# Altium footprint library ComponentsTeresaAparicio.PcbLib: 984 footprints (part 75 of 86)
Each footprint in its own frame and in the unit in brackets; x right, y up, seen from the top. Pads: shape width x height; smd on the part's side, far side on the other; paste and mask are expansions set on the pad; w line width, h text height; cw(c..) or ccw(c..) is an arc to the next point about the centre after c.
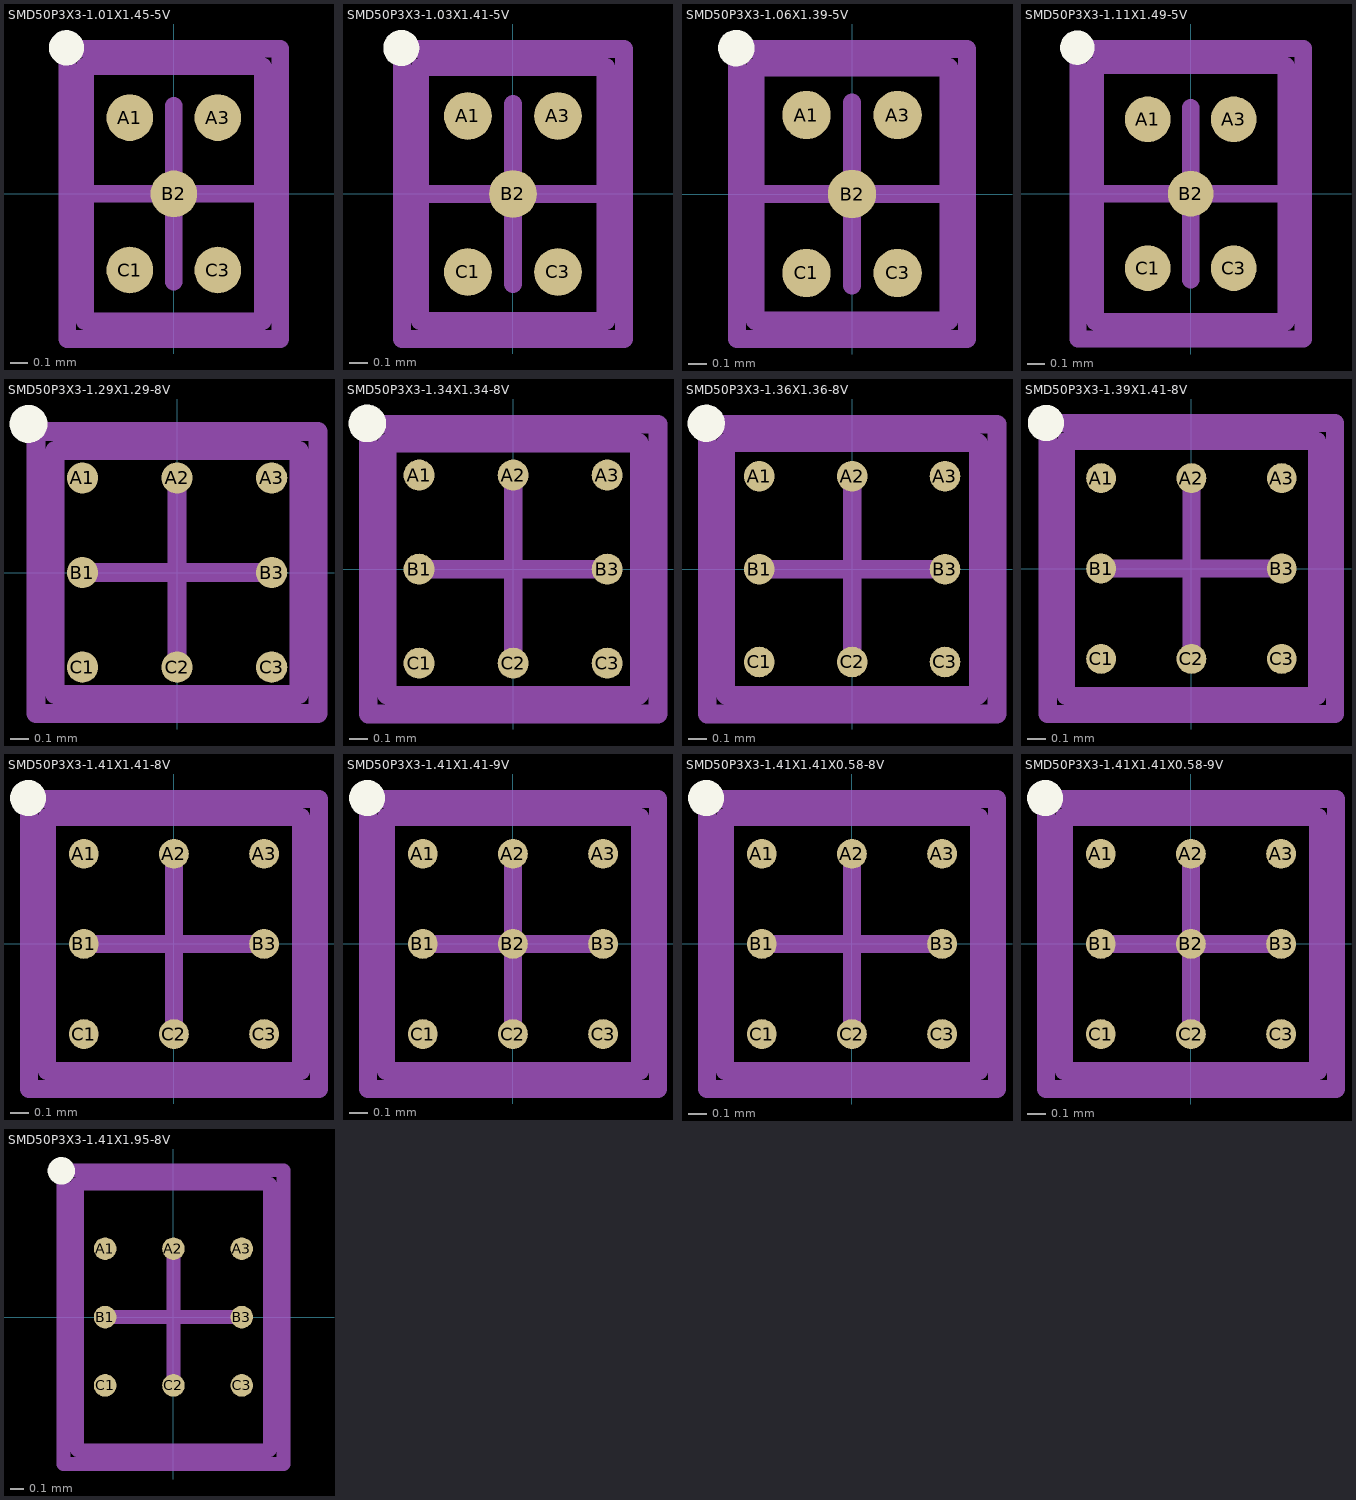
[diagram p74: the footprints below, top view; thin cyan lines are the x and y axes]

## SMD50P3X3-1.01X1.45-5V [mm] "Micro SMD, 5-Leads, Body 1.45x1.01mm, Pitch 0.5mm, NSC Recommended"
height 0.68
pads (5):
  round 0.265 smd paste-0.132 mask+0.05: A1(-0.25,0.433) A3(0.25,0.433) B2(0,0) C1(-0.25,-0.433) C3(0.25,-0.433)
Top Overlay:
  circle w0.1: c-0.61,0.83 r0.05
Top Paste:
  circle w0.05: c-0.2,0.383 r0.025
  circle w0.05: c-0.35,0.533 r0.025
  circle w0.05: c-0.2,0.533 r0.025
  circle w0.05: c-0.35,0.383 r0.025
  circle w0.05: c-0.2,-0.383 r0.025
  circle w0.05: c-0.35,-0.533 r0.025
  circle w0.05: c-0.35,-0.383 r0.025
  circle w0.05: c-0.2,-0.533 r0.025
  circle w0.05: c0.2,-0.383 r0.025
  circle w0.05: c0.35,-0.533 r0.025
  circle w0.05: c0.2,-0.533 r0.025
  circle w0.05: c0.35,-0.383 r0.025
  circle w0.05: c0.2,0.383 r0.025
  circle w0.05: c0.35,0.533 r0.025
  circle w0.05: c0.35,0.383 r0.025
  circle w0.05: c0.2,0.533 r0.025
  circle w0.05: c-0.075,0.075 r0.025
  circle w0.05: c0.075,-0.075 r0.025
  circle w0.05: c0.075,0.075 r0.025
  circle w0.05: c-0.075,-0.075 r0.025
  rectangle: -0.35,0.383 -0.2,0.533
  region: -0.2,0.383 -0.35,0.383 -0.35,0.333 -0.2,0.333
  region: -0.35,0.383 -0.35,0.533 -0.4,0.533 -0.4,0.383
  rectangle: -0.35,0.533 -0.2,0.583
  region: -0.2,0.533 -0.2,0.383 -0.15,0.383 -0.15,0.533
  region: -0.2,-0.533 -0.2,-0.383 -0.35,-0.383 -0.35,-0.533
  region: -0.2,-0.383 -0.2,-0.533 -0.15,-0.533 -0.15,-0.383
  region: -0.2,-0.533 -0.35,-0.533 -0.35,-0.583 -0.2,-0.583
  region: -0.35,-0.533 -0.35,-0.383 -0.4,-0.383 -0.4,-0.533
  rectangle: -0.35,-0.383 -0.2,-0.333
  region: 0.35,-0.383 0.2,-0.383 0.2,-0.533 0.35,-0.533
  rectangle: 0.2,-0.383 0.35,-0.333
  region: 0.35,-0.383 0.35,-0.533 0.4,-0.533 0.4,-0.383
  region: 0.35,-0.533 0.2,-0.533 0.2,-0.583 0.35,-0.583
  region: 0.2,-0.533 0.2,-0.383 0.15,-0.383 0.15,-0.533
  region: 0.2,0.533 0.2,0.383 0.35,0.383 0.35,0.533
  region: 0.2,0.383 0.2,0.533 0.15,0.533 0.15,0.383
  rectangle: 0.2,0.533 0.35,0.583
  region: 0.35,0.533 0.35,0.383 0.4,0.383 0.4,0.533
  region: 0.35,0.383 0.2,0.383 0.2,0.333 0.35,0.333
  region: 0.075,-0.075 -0.075,-0.075 -0.075,-0.125 0.075,-0.125
  region: 0.075,0.075 0.075,-0.075 0.125,-0.075 0.125,0.075
  rectangle: -0.075,0.075 0.075,0.125
  region: -0.075,-0.075 -0.075,0.075 -0.125,0.075 -0.125,-0.075
  region: -0.075,0.075 -0.075,-0.075 0.075,-0.075 0.075,0.075
Mechanical 13:
  lines w0.1: -0.505,-0.725 -0.505,0.725 0.505,0.725 0.505,-0.725 -0.505,-0.725
Mechanical 15:
  lines w0.1: -0.5,0 0.5,0 ; 0,-0.5 0,0.5 ; -0.605,-0.825 -0.605,0.825 0.605,0.825 0.605,-0.825 -0.605,-0.825
3D body: height 0.68, standoff 0, extent -0.504,-0.724 0.504,0.724

## SMD50P3X3-1.03X1.41-5V [mm] "Micro SMD, 5-Leads, Body 1.41x1.03mm, Pitch 0.5mm, NSC Recommended"
height 0.68
pads (5):
  round 0.265 smd paste-0.132 mask+0.05: A1(-0.25,0.433) A3(0.25,0.433) B2(0,0) C1(-0.25,-0.433) C3(0.25,-0.433)
Top Overlay:
  circle w0.1: c-0.62,0.81 r0.05
Top Paste:
  circle w0.05: c-0.2,0.383 r0.025
  circle w0.05: c-0.35,0.533 r0.025
  circle w0.05: c-0.2,0.533 r0.025
  circle w0.05: c-0.35,0.383 r0.025
  circle w0.05: c-0.2,-0.383 r0.025
  circle w0.05: c-0.35,-0.533 r0.025
  circle w0.05: c-0.35,-0.383 r0.025
  circle w0.05: c-0.2,-0.533 r0.025
  circle w0.05: c0.2,-0.383 r0.025
  circle w0.05: c0.35,-0.533 r0.025
  circle w0.05: c0.2,-0.533 r0.025
  circle w0.05: c0.35,-0.383 r0.025
  circle w0.05: c0.2,0.383 r0.025
  circle w0.05: c0.35,0.533 r0.025
  circle w0.05: c0.35,0.383 r0.025
  circle w0.05: c0.2,0.533 r0.025
  circle w0.05: c-0.075,0.075 r0.025
  circle w0.05: c0.075,-0.075 r0.025
  circle w0.05: c0.075,0.075 r0.025
  circle w0.05: c-0.075,-0.075 r0.025
  rectangle: -0.35,0.383 -0.2,0.533
  region: -0.2,0.383 -0.35,0.383 -0.35,0.333 -0.2,0.333
  region: -0.35,0.383 -0.35,0.533 -0.4,0.533 -0.4,0.383
  rectangle: -0.35,0.533 -0.2,0.583
  region: -0.2,0.533 -0.2,0.383 -0.15,0.383 -0.15,0.533
  region: -0.2,-0.533 -0.2,-0.383 -0.35,-0.383 -0.35,-0.533
  region: -0.2,-0.383 -0.2,-0.533 -0.15,-0.533 -0.15,-0.383
  region: -0.2,-0.533 -0.35,-0.533 -0.35,-0.583 -0.2,-0.583
  region: -0.35,-0.533 -0.35,-0.383 -0.4,-0.383 -0.4,-0.533
  rectangle: -0.35,-0.383 -0.2,-0.333
  region: 0.35,-0.383 0.2,-0.383 0.2,-0.533 0.35,-0.533
  rectangle: 0.2,-0.383 0.35,-0.333
  region: 0.35,-0.383 0.35,-0.533 0.4,-0.533 0.4,-0.383
  region: 0.35,-0.533 0.2,-0.533 0.2,-0.583 0.35,-0.583
  region: 0.2,-0.533 0.2,-0.383 0.15,-0.383 0.15,-0.533
  region: 0.2,0.533 0.2,0.383 0.35,0.383 0.35,0.533
  region: 0.2,0.383 0.2,0.533 0.15,0.533 0.15,0.383
  rectangle: 0.2,0.533 0.35,0.583
  region: 0.35,0.533 0.35,0.383 0.4,0.383 0.4,0.533
  region: 0.35,0.383 0.2,0.383 0.2,0.333 0.35,0.333
  region: 0.075,-0.075 -0.075,-0.075 -0.075,-0.125 0.075,-0.125
  region: 0.075,0.075 0.075,-0.075 0.125,-0.075 0.125,0.075
  rectangle: -0.075,0.075 0.075,0.125
  region: -0.075,-0.075 -0.075,0.075 -0.125,0.075 -0.125,-0.075
  region: -0.075,0.075 -0.075,-0.075 0.075,-0.075 0.075,0.075
Mechanical 13:
  lines w0.1: -0.515,-0.705 0.515,-0.705 0.515,0.705 -0.515,0.705 -0.515,-0.705
Mechanical 15:
  lines w0.1: -0.5,0 0.5,0 ; 0,-0.5 0,0.5 ; -0.615,-0.805 0.615,-0.805 0.615,0.805 -0.615,0.805 -0.615,-0.805
3D body: height 0.68, standoff 0, extent -0.514,-0.704 0.514,0.704

## SMD50P3X3-1.06X1.39-5V [mm] "Micro SMD, 5-Leads, Body 1.39x1.06mm, Pitch 0.5mm, NSC Recommended"
height 0.68
pads (5):
  round 0.265 smd paste-0.132 mask+0.05: A1(-0.25,0.433) A3(0.25,0.433) B2(0,0) C1(-0.25,-0.433) C3(0.25,-0.433)
Top Overlay:
  circle w0.1: c-0.635,0.8 r0.05
Top Paste:
  circle w0.05: c0.2,-0.383 r0.025
  circle w0.05: c0.35,-0.533 r0.025
  circle w0.05: c0.35,-0.383 r0.025
  circle w0.05: c0.2,-0.533 r0.025
  circle w0.05: c-0.35,-0.383 r0.025
  circle w0.05: c-0.2,-0.533 r0.025
  circle w0.05: c-0.2,-0.383 r0.025
  circle w0.05: c-0.35,-0.533 r0.025
  circle w0.05: c-0.075,0.075 r0.025
  circle w0.05: c0.075,-0.075 r0.025
  circle w0.05: c0.075,0.075 r0.025
  circle w0.05: c-0.075,-0.075 r0.025
  circle w0.05: c0.2,0.533 r0.025
  circle w0.05: c0.35,0.383 r0.025
  circle w0.05: c0.35,0.533 r0.025
  circle w0.05: c0.2,0.383 r0.025
  circle w0.05: c-0.35,0.533 r0.025
  circle w0.05: c-0.2,0.383 r0.025
  circle w0.05: c-0.2,0.533 r0.025
  circle w0.05: c-0.35,0.383 r0.025
  region: 0.35,-0.533 0.2,-0.533 0.2,-0.583 0.35,-0.583
  region: 0.35,-0.383 0.35,-0.533 0.4,-0.533 0.4,-0.383
  rectangle: 0.2,-0.383 0.35,-0.333
  region: 0.2,-0.533 0.2,-0.383 0.15,-0.383 0.15,-0.533
  region: 0.2,-0.383 0.2,-0.533 0.35,-0.533 0.35,-0.383
  region: -0.2,-0.533 -0.35,-0.533 -0.35,-0.583 -0.2,-0.583
  region: -0.2,-0.383 -0.2,-0.533 -0.15,-0.533 -0.15,-0.383
  rectangle: -0.35,-0.383 -0.2,-0.333
  region: -0.35,-0.533 -0.35,-0.383 -0.4,-0.383 -0.4,-0.533
  region: -0.35,-0.383 -0.35,-0.533 -0.2,-0.533 -0.2,-0.383
  region: 0.075,-0.075 -0.075,-0.075 -0.075,-0.125 0.075,-0.125
  region: 0.075,0.075 0.075,-0.075 0.125,-0.075 0.125,0.075
  rectangle: -0.075,0.075 0.075,0.125
  region: -0.075,-0.075 -0.075,0.075 -0.125,0.075 -0.125,-0.075
  region: -0.075,0.075 -0.075,-0.075 0.075,-0.075 0.075,0.075
  region: 0.35,0.383 0.2,0.383 0.2,0.333 0.35,0.333
  region: 0.35,0.533 0.35,0.383 0.4,0.383 0.4,0.533
  rectangle: 0.2,0.533 0.35,0.583
  region: 0.2,0.383 0.2,0.533 0.15,0.533 0.15,0.383
  region: 0.2,0.533 0.2,0.383 0.35,0.383 0.35,0.533
  region: -0.2,0.383 -0.35,0.383 -0.35,0.333 -0.2,0.333
  region: -0.2,0.533 -0.2,0.383 -0.15,0.383 -0.15,0.533
  rectangle: -0.35,0.533 -0.2,0.583
  region: -0.35,0.383 -0.35,0.533 -0.4,0.533 -0.4,0.383
  region: -0.35,0.533 -0.35,0.383 -0.2,0.383 -0.2,0.533
Mechanical 13:
  lines w0.1: -0.53,-0.695 0.53,-0.695 0.53,0.695 -0.53,0.695 -0.53,-0.695
Mechanical 15:
  lines w0.1: -0.5,0 0.5,0 ; 0,-0.5 0,0.5 ; -0.63,-0.795 0.63,-0.795 0.63,0.795 -0.63,0.795 -0.63,-0.795
3D body: height 0.68, standoff 0, extent -0.53,-0.695 0.53,0.695

## SMD50P3X3-1.11X1.49-5V [mm] "Micro SMD, 5-Leads, Body 1.49x1.11mm, Pitch 0.5mm, NSC Recommended"
height 0.68
pads (5):
  round 0.265 smd paste-0.132 mask+0.05: A1(-0.25,0.433) A3(0.25,0.433) B2(0,0) C1(-0.25,-0.433) C3(0.25,-0.433)
Top Overlay:
  circle w0.1: c-0.66,0.85 r0.05
Top Paste:
  circle w0.05: c-0.35,0.383 r0.025
  circle w0.05: c-0.2,0.533 r0.025
  circle w0.05: c-0.2,0.383 r0.025
  circle w0.05: c-0.35,0.533 r0.025
  circle w0.05: c0.2,0.383 r0.025
  circle w0.05: c0.35,0.533 r0.025
  circle w0.05: c0.35,0.383 r0.025
  circle w0.05: c0.2,0.533 r0.025
  circle w0.05: c-0.075,-0.075 r0.025
  circle w0.05: c0.075,0.075 r0.025
  circle w0.05: c0.075,-0.075 r0.025
  circle w0.05: c-0.075,0.075 r0.025
  circle w0.05: c-0.35,-0.533 r0.025
  circle w0.05: c-0.2,-0.383 r0.025
  circle w0.05: c-0.2,-0.533 r0.025
  circle w0.05: c-0.35,-0.383 r0.025
  circle w0.05: c0.2,-0.533 r0.025
  circle w0.05: c0.35,-0.383 r0.025
  circle w0.05: c0.35,-0.533 r0.025
  circle w0.05: c0.2,-0.383 r0.025
  region: -0.35,0.533 -0.35,0.383 -0.2,0.383 -0.2,0.533
  region: -0.35,0.383 -0.35,0.533 -0.4,0.533 -0.4,0.383
  rectangle: -0.35,0.533 -0.2,0.583
  region: -0.2,0.533 -0.2,0.383 -0.15,0.383 -0.15,0.533
  region: -0.2,0.383 -0.35,0.383 -0.35,0.333 -0.2,0.333
  region: 0.2,0.533 0.2,0.383 0.35,0.383 0.35,0.533
  region: 0.2,0.383 0.2,0.533 0.15,0.533 0.15,0.383
  rectangle: 0.2,0.533 0.35,0.583
  region: 0.35,0.533 0.35,0.383 0.4,0.383 0.4,0.533
  region: 0.35,0.383 0.2,0.383 0.2,0.333 0.35,0.333
  region: -0.075,0.075 -0.075,-0.075 0.075,-0.075 0.075,0.075
  region: -0.075,-0.075 -0.075,0.075 -0.125,0.075 -0.125,-0.075
  rectangle: -0.075,0.075 0.075,0.125
  region: 0.075,0.075 0.075,-0.075 0.125,-0.075 0.125,0.075
  region: 0.075,-0.075 -0.075,-0.075 -0.075,-0.125 0.075,-0.125
  region: -0.35,-0.383 -0.35,-0.533 -0.2,-0.533 -0.2,-0.383
  region: -0.35,-0.533 -0.35,-0.383 -0.4,-0.383 -0.4,-0.533
  rectangle: -0.35,-0.383 -0.2,-0.333
  region: -0.2,-0.383 -0.2,-0.533 -0.15,-0.533 -0.15,-0.383
  region: -0.2,-0.533 -0.35,-0.533 -0.35,-0.583 -0.2,-0.583
  region: 0.2,-0.383 0.2,-0.533 0.35,-0.533 0.35,-0.383
  region: 0.2,-0.533 0.2,-0.383 0.15,-0.383 0.15,-0.533
  rectangle: 0.2,-0.383 0.35,-0.333
  region: 0.35,-0.383 0.35,-0.533 0.4,-0.533 0.4,-0.383
  region: 0.35,-0.533 0.2,-0.533 0.2,-0.583 0.35,-0.583
Mechanical 13:
  lines w0.1: -0.555,-0.745 0.555,-0.745 0.555,0.745 -0.555,0.745 -0.555,-0.745
Mechanical 15:
  lines w0.1: -0.5,0 0.5,0 ; 0,-0.5 0,0.5 ; -0.655,-0.845 0.655,-0.845 0.655,0.845 -0.655,0.845 -0.655,-0.845
3D body: height 0.68, standoff 0, extent -0.555,-0.745 0.555,0.745

## SMD50P3X3-1.29X1.29-8V [mm] "Micro SMD, 8-Leads, Body 1.29x1.29mm, Pitch 0.5mm, NSC Recommended"
height 0.58
pads (8):
  round 0.165 smd paste-0.082 mask+0.05: A1(-0.5,0.5) A2(0,0.5) A3(0.5,0.5) B1(-0.5,0) B3(0.5,0) C1(-0.5,-0.5) C2(0,-0.5) C3(0.5,-0.5)
Top Overlay:
  circle w0.1: c-0.785,0.785 r0.05
Top Paste:
  circle w0.05: c0.625,0.425 r0.025
  circle w0.05: c0.425,0.625 r0.025
  circle w0.05: c0.425,0.425 r0.025
  circle w0.05: c0.625,0.625 r0.025
  circle w0.05: c-0.425,0.425 r0.025
  circle w0.05: c-0.625,0.625 r0.025
  circle w0.05: c-0.625,0.425 r0.025
  circle w0.05: c-0.425,0.625 r0.025
  circle w0.05: c0.1,0.425 r0.025
  circle w0.05: c-0.1,0.625 r0.025
  circle w0.05: c-0.1,0.425 r0.025
  circle w0.05: c0.1,0.625 r0.025
  circle w0.05: c0.1,-0.425 r0.025
  circle w0.05: c-0.1,-0.625 r0.025
  circle w0.05: c-0.1,-0.425 r0.025
  circle w0.05: c0.1,-0.625 r0.025
  circle w0.05: c-0.425,-0.425 r0.025
  circle w0.05: c-0.625,-0.625 r0.025
  circle w0.05: c-0.625,-0.425 r0.025
  circle w0.05: c-0.425,-0.625 r0.025
  circle w0.05: c0.625,-0.425 r0.025
  circle w0.05: c0.425,-0.625 r0.025
  circle w0.05: c0.425,-0.425 r0.025
  circle w0.05: c0.625,-0.625 r0.025
  circle w0.05: c0.625,-0.1 r0.025
  circle w0.05: c0.425,0.1 r0.025
  circle w0.05: c0.425,-0.1 r0.025
  circle w0.05: c0.625,0.1 r0.025
  circle w0.05: c-0.425,0.1 r0.025
  circle w0.05: c-0.625,-0.1 r0.025
  circle w0.05: c-0.625,0.1 r0.025
  circle w0.05: c-0.425,-0.1 r0.025
  rectangle: 0.425,0.375 0.625,0.425
  region: 0.625,0.675 0.425,0.675 0.425,0.625 0.625,0.625
  region: 0.375,0.625 0.375,0.425 0.425,0.425 0.425,0.625
  region: 0.425,0.625 0.425,0.425 0.625,0.425 0.625,0.625
  region: 0.675,0.425 0.675,0.625 0.625,0.625 0.625,0.425
  rectangle: -0.625,0.375 -0.425,0.425
  region: -0.425,0.675 -0.625,0.675 -0.625,0.625 -0.425,0.625
  region: -0.675,0.625 -0.675,0.425 -0.625,0.425 -0.625,0.625
  region: -0.625,0.625 -0.625,0.425 -0.425,0.425 -0.425,0.625
  region: -0.375,0.425 -0.375,0.625 -0.425,0.625 -0.425,0.425
  rectangle: -0.1,0.375 0.1,0.425
  region: 0.1,0.675 -0.1,0.675 -0.1,0.625 0.1,0.625
  region: -0.15,0.625 -0.15,0.425 -0.1,0.425 -0.1,0.625
  region: -0.1,0.625 -0.1,0.425 0.1,0.425 0.1,0.625
  region: 0.15,0.425 0.15,0.625 0.1,0.625 0.1,0.425
  region: 0.15,-0.625 0.15,-0.425 0.1,-0.425 0.1,-0.625
  region: -0.1,-0.425 -0.1,-0.625 0.1,-0.625 0.1,-0.425
  region: -0.15,-0.425 -0.15,-0.625 -0.1,-0.625 -0.1,-0.425
  region: 0.1,-0.375 -0.1,-0.375 -0.1,-0.425 0.1,-0.425
  rectangle: -0.1,-0.675 0.1,-0.625
  region: -0.375,-0.625 -0.375,-0.425 -0.425,-0.425 -0.425,-0.625
  region: -0.625,-0.425 -0.625,-0.625 -0.425,-0.625 -0.425,-0.425
  region: -0.675,-0.425 -0.675,-0.625 -0.625,-0.625 -0.625,-0.425
  region: -0.425,-0.375 -0.625,-0.375 -0.625,-0.425 -0.425,-0.425
  rectangle: -0.625,-0.675 -0.425,-0.625
  region: 0.675,-0.625 0.675,-0.425 0.625,-0.425 0.625,-0.625
  region: 0.425,-0.425 0.425,-0.625 0.625,-0.625 0.625,-0.425
  region: 0.375,-0.425 0.375,-0.625 0.425,-0.625 0.425,-0.425
  region: 0.625,-0.375 0.425,-0.375 0.425,-0.425 0.625,-0.425
  rectangle: 0.425,-0.675 0.625,-0.625
  rectangle: 0.425,-0.15 0.625,-0.1
  region: 0.625,0.15 0.425,0.15 0.425,0.1 0.625,0.1
  region: 0.375,0.1 0.375,-0.1 0.425,-0.1 0.425,0.1
  region: 0.425,0.1 0.425,-0.1 0.625,-0.1 0.625,0.1
  region: 0.675,-0.1 0.675,0.1 0.625,0.1 0.625,-0.1
  region: -0.375,-0.1 -0.375,0.1 -0.425,0.1 -0.425,-0.1
  region: -0.625,0.1 -0.625,-0.1 -0.425,-0.1 -0.425,0.1
  region: -0.675,0.1 -0.675,-0.1 -0.625,-0.1 -0.625,0.1
  region: -0.425,0.15 -0.625,0.15 -0.625,0.1 -0.425,0.1
  rectangle: -0.625,-0.15 -0.425,-0.1
Mechanical 13:
  lines w0.1: -0.645,-0.645 0.645,-0.645 0.645,0.645 -0.645,0.645 -0.645,-0.645
Mechanical 15:
  lines w0.1: -0.5,0 0.5,0 ; 0,-0.5 0,0.5 ; -0.745,-0.745 0.745,-0.745 0.745,0.745 -0.745,0.745 -0.745,-0.745
3D body: height 0.58, standoff 0, extent -0.644,-0.644 0.644,0.644

## SMD50P3X3-1.34X1.34-8V [mm] "Micro SMD, 8-Leads, Body 1.34x1.34mm, Pitch 0.5mm, NSC Recommended"
height 0.95
pads (8):
  round 0.165 smd paste-0.082 mask+0.05: A1(-0.5,0.5) A2(0,0.5) A3(0.5,0.5) B1(-0.5,0) B3(0.5,0) C1(-0.5,-0.5) C2(0,-0.5) C3(0.5,-0.5)
Top Overlay:
  circle w0.1: c-0.775,0.775 r0.05
Top Paste:
  circle w0.05: c-0.625,-0.625 r0.025
  circle w0.05: c-0.425,-0.425 r0.025
  circle w0.05: c-0.625,-0.425 r0.025
  circle w0.05: c-0.425,-0.625 r0.025
  circle w0.05: c0.425,-0.625 r0.025
  circle w0.05: c0.625,-0.425 r0.025
  circle w0.05: c0.425,-0.425 r0.025
  circle w0.05: c0.625,-0.625 r0.025
  circle w0.05: c0.425,0.425 r0.025
  circle w0.05: c0.625,0.625 r0.025
  circle w0.05: c0.425,0.625 r0.025
  circle w0.05: c0.625,0.425 r0.025
  circle w0.05: c-0.625,0.425 r0.025
  circle w0.05: c-0.425,0.625 r0.025
  circle w0.05: c-0.625,0.625 r0.025
  circle w0.05: c-0.425,0.425 r0.025
  circle w0.05: c0.1,0.425 r0.025
  circle w0.05: c-0.1,0.625 r0.025
  circle w0.05: c0.1,0.625 r0.025
  circle w0.05: c-0.1,0.425 r0.025
  circle w0.05: c-0.1,-0.425 r0.025
  circle w0.05: c0.1,-0.625 r0.025
  circle w0.05: c-0.1,-0.625 r0.025
  circle w0.05: c0.1,-0.425 r0.025
  circle w0.05: c0.425,-0.1 r0.025
  circle w0.05: c0.625,0.1 r0.025
  circle w0.05: c0.625,-0.1 r0.025
  circle w0.05: c0.425,0.1 r0.025
  circle w0.05: c-0.425,0.1 r0.025
  circle w0.05: c-0.625,-0.1 r0.025
  circle w0.05: c-0.625,0.1 r0.025
  circle w0.05: c-0.425,-0.1 r0.025
  region: -0.425,-0.625 -0.625,-0.625 -0.625,-0.675 -0.425,-0.675
  rectangle: -0.625,-0.625 -0.425,-0.425
  rectangle: -0.625,-0.425 -0.425,-0.375
  region: -0.625,-0.625 -0.625,-0.425 -0.675,-0.425 -0.675,-0.625
  region: -0.425,-0.425 -0.425,-0.625 -0.375,-0.625 -0.375,-0.425
  region: 0.625,-0.625 0.425,-0.625 0.425,-0.675 0.625,-0.675
  rectangle: 0.425,-0.625 0.625,-0.425
  rectangle: 0.425,-0.425 0.625,-0.375
  region: 0.425,-0.625 0.425,-0.425 0.375,-0.425 0.375,-0.625
  region: 0.625,-0.425 0.625,-0.625 0.675,-0.625 0.675,-0.425
  region: 0.625,0.425 0.425,0.425 0.425,0.375 0.625,0.375
  rectangle: 0.425,0.425 0.625,0.625
  rectangle: 0.425,0.625 0.625,0.675
  region: 0.425,0.425 0.425,0.625 0.375,0.625 0.375,0.425
  region: 0.625,0.625 0.625,0.425 0.675,0.425 0.675,0.625
  region: -0.425,0.425 -0.625,0.425 -0.625,0.375 -0.425,0.375
  rectangle: -0.625,0.425 -0.425,0.625
  rectangle: -0.625,0.625 -0.425,0.675
  region: -0.625,0.425 -0.625,0.625 -0.675,0.625 -0.675,0.425
  region: -0.425,0.625 -0.425,0.425 -0.375,0.425 -0.375,0.625
  region: 0.1,0.625 0.1,0.425 0.15,0.425 0.15,0.625
  region: -0.1,0.425 -0.1,0.625 -0.15,0.625 -0.15,0.425
  rectangle: -0.1,0.625 0.1,0.675
  rectangle: -0.1,0.425 0.1,0.625
  region: 0.1,0.425 -0.1,0.425 -0.1,0.375 0.1,0.375
  region: 0.1,-0.375 -0.1,-0.375 -0.1,-0.425 0.1,-0.425
  rectangle: -0.1,-0.625 0.1,-0.425
  rectangle: -0.1,-0.675 0.1,-0.625
  region: -0.15,-0.425 -0.15,-0.625 -0.1,-0.625 -0.1,-0.425
  region: 0.15,-0.625 0.15,-0.425 0.1,-0.425 0.1,-0.625
  region: 0.375,0.1 0.375,-0.1 0.425,-0.1 0.425,0.1
  region: 0.625,-0.1 0.625,0.1 0.425,0.1 0.425,-0.1
  region: 0.675,-0.1 0.675,0.1 0.625,0.1 0.625,-0.1
  rectangle: 0.425,-0.15 0.625,-0.1
  region: 0.625,0.15 0.425,0.15 0.425,0.1 0.625,0.1
  region: -0.375,-0.1 -0.375,0.1 -0.425,0.1 -0.425,-0.1
  region: -0.625,0.1 -0.625,-0.1 -0.425,-0.1 -0.425,0.1
  region: -0.675,0.1 -0.675,-0.1 -0.625,-0.1 -0.625,0.1
  region: -0.425,0.15 -0.625,0.15 -0.625,0.1 -0.425,0.1
  rectangle: -0.625,-0.15 -0.425,-0.1
Mechanical 13:
  lines w0.1: -0.67,-0.67 0.67,-0.67 0.67,0.67 -0.67,0.67 -0.67,-0.67
Mechanical 15:
  lines w0.1: -0.5,0 0.5,0 ; 0,-0.5 0,0.5 ; -0.77,-0.77 0.77,-0.77 0.77,0.77 -0.77,0.77 -0.77,-0.77
3D body: height 0.95, standoff 0, extent -0.669,-0.669 0.669,0.669

## SMD50P3X3-1.36X1.36-8V [mm] "Micro SMD, 8-Leads, Body 1.36x1.36mm, Pitch 0.5mm, NSC Recommended"
height 0.58
pads (8):
  round 0.165 smd paste-0.082 mask+0.05: A1(-0.5,0.5) A2(0,0.5) A3(0.5,0.5) B1(-0.5,0) B3(0.5,0) C1(-0.5,-0.5) C2(0,-0.5) C3(0.5,-0.5)
Top Overlay:
  circle w0.1: c-0.785,0.785 r0.05
Top Paste:
  circle w0.05: c-0.425,-0.1 r0.025
  circle w0.05: c-0.625,0.1 r0.025
  circle w0.05: c-0.625,-0.1 r0.025
  circle w0.05: c-0.425,0.1 r0.025
  circle w0.05: c0.625,0.1 r0.025
  circle w0.05: c0.425,-0.1 r0.025
  circle w0.05: c0.425,0.1 r0.025
  circle w0.05: c0.625,-0.1 r0.025
  circle w0.05: c0.625,-0.625 r0.025
  circle w0.05: c0.425,-0.425 r0.025
  circle w0.05: c0.425,-0.625 r0.025
  circle w0.05: c0.625,-0.425 r0.025
  circle w0.05: c-0.425,-0.625 r0.025
  circle w0.05: c-0.625,-0.425 r0.025
  circle w0.05: c-0.625,-0.625 r0.025
  circle w0.05: c-0.425,-0.425 r0.025
  circle w0.05: c0.1,-0.625 r0.025
  circle w0.05: c-0.1,-0.425 r0.025
  circle w0.05: c-0.1,-0.625 r0.025
  circle w0.05: c0.1,-0.425 r0.025
  circle w0.05: c0.1,0.625 r0.025
  circle w0.05: c-0.1,0.425 r0.025
  circle w0.05: c-0.1,0.625 r0.025
  circle w0.05: c0.1,0.425 r0.025
  circle w0.05: c-0.425,0.625 r0.025
  circle w0.05: c-0.625,0.425 r0.025
  circle w0.05: c-0.625,0.625 r0.025
  circle w0.05: c-0.425,0.425 r0.025
  circle w0.05: c0.625,0.625 r0.025
  circle w0.05: c0.425,0.425 r0.025
  circle w0.05: c0.425,0.625 r0.025
  circle w0.05: c0.625,0.425 r0.025
  rectangle: -0.625,-0.15 -0.425,-0.1
  region: -0.425,0.15 -0.625,0.15 -0.625,0.1 -0.425,0.1
  region: -0.675,0.1 -0.675,-0.1 -0.625,-0.1 -0.625,0.1
  region: -0.625,0.1 -0.625,-0.1 -0.425,-0.1 -0.425,0.1
  region: -0.375,-0.1 -0.375,0.1 -0.425,0.1 -0.425,-0.1
  region: 0.675,-0.1 0.675,0.1 0.625,0.1 0.625,-0.1
  region: 0.425,0.1 0.425,-0.1 0.625,-0.1 0.625,0.1
  region: 0.375,0.1 0.375,-0.1 0.425,-0.1 0.425,0.1
  region: 0.625,0.15 0.425,0.15 0.425,0.1 0.625,0.1
  rectangle: 0.425,-0.15 0.625,-0.1
  rectangle: 0.425,-0.675 0.625,-0.625
  region: 0.625,-0.375 0.425,-0.375 0.425,-0.425 0.625,-0.425
  region: 0.375,-0.425 0.375,-0.625 0.425,-0.625 0.425,-0.425
  region: 0.425,-0.425 0.425,-0.625 0.625,-0.625 0.625,-0.425
  region: 0.675,-0.625 0.675,-0.425 0.625,-0.425 0.625,-0.625
  rectangle: -0.625,-0.675 -0.425,-0.625
  region: -0.425,-0.375 -0.625,-0.375 -0.625,-0.425 -0.425,-0.425
  region: -0.675,-0.425 -0.675,-0.625 -0.625,-0.625 -0.625,-0.425
  region: -0.625,-0.425 -0.625,-0.625 -0.425,-0.625 -0.425,-0.425
  region: -0.375,-0.625 -0.375,-0.425 -0.425,-0.425 -0.425,-0.625
  rectangle: -0.1,-0.675 0.1,-0.625
  region: 0.1,-0.375 -0.1,-0.375 -0.1,-0.425 0.1,-0.425
  region: -0.15,-0.425 -0.15,-0.625 -0.1,-0.625 -0.1,-0.425
  region: -0.1,-0.425 -0.1,-0.625 0.1,-0.625 0.1,-0.425
  region: 0.15,-0.625 0.15,-0.425 0.1,-0.425 0.1,-0.625
  region: 0.15,0.425 0.15,0.625 0.1,0.625 0.1,0.425
  region: -0.1,0.625 -0.1,0.425 0.1,0.425 0.1,0.625
  region: -0.15,0.625 -0.15,0.425 -0.1,0.425 -0.1,0.625
  region: 0.1,0.675 -0.1,0.675 -0.1,0.625 0.1,0.625
  rectangle: -0.1,0.375 0.1,0.425
  region: -0.375,0.425 -0.375,0.625 -0.425,0.625 -0.425,0.425
  region: -0.625,0.625 -0.625,0.425 -0.425,0.425 -0.425,0.625
  region: -0.675,0.625 -0.675,0.425 -0.625,0.425 -0.625,0.625
  region: -0.425,0.675 -0.625,0.675 -0.625,0.625 -0.425,0.625
  rectangle: -0.625,0.375 -0.425,0.425
  region: 0.675,0.425 0.675,0.625 0.625,0.625 0.625,0.425
  region: 0.425,0.625 0.425,0.425 0.625,0.425 0.625,0.625
  region: 0.375,0.625 0.375,0.425 0.425,0.425 0.425,0.625
  region: 0.625,0.675 0.425,0.675 0.425,0.625 0.625,0.625
  rectangle: 0.425,0.375 0.625,0.425
Mechanical 13:
  lines w0.1: -0.68,-0.68 -0.68,0.68 0.68,0.68 0.68,-0.68 -0.68,-0.68
Mechanical 15:
  lines w0.1: -0.5,0 0.5,0 ; 0,-0.5 0,0.5 ; -0.78,-0.78 -0.78,0.78 0.78,0.78 0.78,-0.78 -0.78,-0.78
3D body: height 0.58, standoff 0, extent -0.679,-0.679 0.679,0.679

## SMD50P3X3-1.39X1.41-8V [mm] "Micro SMD, 8-Leads, Body 1.41x1.39mm, Pitch 0.5mm, NSC Recommended"
height 0.95
pads (8):
  round 0.165 smd paste-0.082 mask+0.05: A1(-0.5,0.5) A2(0,0.5) A3(0.5,0.5) B1(-0.5,0) B3(0.5,0) C1(-0.5,-0.5) C2(0,-0.5) C3(0.5,-0.5)
Top Overlay:
  circle w0.1: c-0.805,0.805 r0.05
Top Paste:
  circle w0.05: c0.625,-0.1 r0.025
  circle w0.05: c0.425,0.1 r0.025
  circle w0.05: c0.625,0.1 r0.025
  circle w0.05: c0.425,-0.1 r0.025
  circle w0.05: c-0.1,-0.625 r0.025
  circle w0.05: c0.1,-0.425 r0.025
  circle w0.05: c0.1,-0.625 r0.025
  circle w0.05: c-0.1,-0.425 r0.025
  circle w0.05: c-0.625,0.1 r0.025
  circle w0.05: c-0.425,-0.1 r0.025
  circle w0.05: c-0.625,-0.1 r0.025
  circle w0.05: c-0.425,0.1 r0.025
  circle w0.05: c0.1,0.625 r0.025
  circle w0.05: c-0.1,0.425 r0.025
  circle w0.05: c-0.1,0.625 r0.025
  circle w0.05: c0.1,0.425 r0.025
  circle w0.05: c0.625,0.425 r0.025
  circle w0.05: c0.425,0.625 r0.025
  circle w0.05: c0.625,0.625 r0.025
  circle w0.05: c0.425,0.425 r0.025
  circle w0.05: c0.425,-0.625 r0.025
  circle w0.05: c0.625,-0.425 r0.025
  circle w0.05: c0.625,-0.625 r0.025
  circle w0.05: c0.425,-0.425 r0.025
  circle w0.05: c-0.625,-0.425 r0.025
  circle w0.05: c-0.425,-0.625 r0.025
  circle w0.05: c-0.625,-0.625 r0.025
  circle w0.05: c-0.425,-0.425 r0.025
  circle w0.05: c-0.425,0.625 r0.025
  circle w0.05: c-0.625,0.425 r0.025
  circle w0.05: c-0.625,0.625 r0.025
  circle w0.05: c-0.425,0.425 r0.025
  rectangle: 0.425,-0.15 0.625,-0.1
  region: 0.625,0.1 0.425,0.1 0.425,-0.1 0.625,-0.1
  region: 0.625,0.15 0.425,0.15 0.425,0.1 0.625,0.1
  region: 0.675,-0.1 0.675,0.1 0.625,0.1 0.625,-0.1
  region: 0.375,0.1 0.375,-0.1 0.425,-0.1 0.425,0.1
  region: -0.15,-0.425 -0.15,-0.625 -0.1,-0.625 -0.1,-0.425
  region: 0.1,-0.625 0.1,-0.425 -0.1,-0.425 -0.1,-0.625
  region: 0.15,-0.625 0.15,-0.425 0.1,-0.425 0.1,-0.625
  rectangle: -0.1,-0.675 0.1,-0.625
  region: 0.1,-0.375 -0.1,-0.375 -0.1,-0.425 0.1,-0.425
  region: -0.425,0.15 -0.625,0.15 -0.625,0.1 -0.425,0.1
  rectangle: -0.625,-0.1 -0.425,0.1
  rectangle: -0.625,-0.15 -0.425,-0.1
  region: -0.675,0.1 -0.675,-0.1 -0.625,-0.1 -0.625,0.1
  region: -0.375,-0.1 -0.375,0.1 -0.425,0.1 -0.425,-0.1
  region: 0.15,0.425 0.15,0.625 0.1,0.625 0.1,0.425
  region: -0.1,0.625 -0.1,0.425 0.1,0.425 0.1,0.625
  region: -0.15,0.625 -0.15,0.425 -0.1,0.425 -0.1,0.625
  region: 0.1,0.675 -0.1,0.675 -0.1,0.625 0.1,0.625
  rectangle: -0.1,0.375 0.1,0.425
  rectangle: 0.425,0.375 0.625,0.425
  region: 0.625,0.625 0.425,0.625 0.425,0.425 0.625,0.425
  region: 0.625,0.675 0.425,0.675 0.425,0.625 0.625,0.625
  region: 0.675,0.425 0.675,0.625 0.625,0.625 0.625,0.425
  region: 0.375,0.625 0.375,0.425 0.425,0.425 0.425,0.625
  region: 0.375,-0.425 0.375,-0.625 0.425,-0.625 0.425,-0.425
  region: 0.625,-0.625 0.625,-0.425 0.425,-0.425 0.425,-0.625
  region: 0.675,-0.625 0.675,-0.425 0.625,-0.425 0.625,-0.625
  rectangle: 0.425,-0.675 0.625,-0.625
  region: 0.625,-0.375 0.425,-0.375 0.425,-0.425 0.625,-0.425
  region: -0.425,-0.375 -0.625,-0.375 -0.625,-0.425 -0.425,-0.425
  rectangle: -0.625,-0.625 -0.425,-0.425
  rectangle: -0.625,-0.675 -0.425,-0.625
  region: -0.675,-0.425 -0.675,-0.625 -0.625,-0.625 -0.625,-0.425
  region: -0.375,-0.625 -0.375,-0.425 -0.425,-0.425 -0.425,-0.625
  region: -0.375,0.425 -0.375,0.625 -0.425,0.625 -0.425,0.425
  region: -0.625,0.625 -0.625,0.425 -0.425,0.425 -0.425,0.625
  region: -0.675,0.625 -0.675,0.425 -0.625,0.425 -0.625,0.625
  region: -0.425,0.675 -0.625,0.675 -0.625,0.625 -0.425,0.625
  rectangle: -0.625,0.375 -0.425,0.425
Mechanical 13:
  lines w0.1: -0.695,-0.705 0.695,-0.705 0.695,0.705 -0.695,0.705 -0.695,-0.705
Mechanical 15:
  lines w0.1: -0.5,0 0.5,0 ; 0,-0.5 0,0.5 ; -0.795,-0.805 0.795,-0.805 0.795,0.805 -0.795,0.805 -0.795,-0.805
3D body: height 0.95, standoff 0, extent -0.694,-0.704 0.694,0.704

## SMD50P3X3-1.41X1.41-8V [mm] "Micro SMD, 8-Leads, Body 1.41x1.41mm, Pitch 0.5mm, NSC Recommended"
height 0.95
pads (8):
  round 0.165 smd paste-0.082 mask+0.05: A1(-0.5,0.5) A2(0,0.5) A3(0.5,0.5) B1(-0.5,0) B3(0.5,0) C1(-0.5,-0.5) C2(0,-0.5) C3(0.5,-0.5)
Top Overlay:
  circle w0.1: c-0.81,0.81 r0.05
Top Paste:
  circle w0.05: c-0.425,-0.1 r0.025
  circle w0.05: c-0.625,0.1 r0.025
  circle w0.05: c-0.625,-0.1 r0.025
  circle w0.05: c-0.425,0.1 r0.025
  circle w0.05: c0.625,0.1 r0.025
  circle w0.05: c0.425,-0.1 r0.025
  circle w0.05: c0.425,0.1 r0.025
  circle w0.05: c0.625,-0.1 r0.025
  circle w0.05: c0.625,-0.625 r0.025
  circle w0.05: c0.425,-0.425 r0.025
  circle w0.05: c0.425,-0.625 r0.025
  circle w0.05: c0.625,-0.425 r0.025
  circle w0.05: c-0.425,-0.625 r0.025
  circle w0.05: c-0.625,-0.425 r0.025
  circle w0.05: c-0.625,-0.625 r0.025
  circle w0.05: c-0.425,-0.425 r0.025
  circle w0.05: c0.1,-0.625 r0.025
  circle w0.05: c-0.1,-0.425 r0.025
  circle w0.05: c-0.1,-0.625 r0.025
  circle w0.05: c0.1,-0.425 r0.025
  circle w0.05: c0.1,0.625 r0.025
  circle w0.05: c-0.1,0.425 r0.025
  circle w0.05: c-0.1,0.625 r0.025
  circle w0.05: c0.1,0.425 r0.025
  circle w0.05: c-0.425,0.625 r0.025
  circle w0.05: c-0.625,0.425 r0.025
  circle w0.05: c-0.625,0.625 r0.025
  circle w0.05: c-0.425,0.425 r0.025
  circle w0.05: c0.625,0.625 r0.025
  circle w0.05: c0.425,0.425 r0.025
  circle w0.05: c0.425,0.625 r0.025
  circle w0.05: c0.625,0.425 r0.025
  rectangle: -0.625,-0.15 -0.425,-0.1
  region: -0.425,0.15 -0.625,0.15 -0.625,0.1 -0.425,0.1
  region: -0.675,0.1 -0.675,-0.1 -0.625,-0.1 -0.625,0.1
  region: -0.625,0.1 -0.625,-0.1 -0.425,-0.1 -0.425,0.1
  region: -0.375,-0.1 -0.375,0.1 -0.425,0.1 -0.425,-0.1
  region: 0.675,-0.1 0.675,0.1 0.625,0.1 0.625,-0.1
  region: 0.425,0.1 0.425,-0.1 0.625,-0.1 0.625,0.1
  region: 0.375,0.1 0.375,-0.1 0.425,-0.1 0.425,0.1
  region: 0.625,0.15 0.425,0.15 0.425,0.1 0.625,0.1
  rectangle: 0.425,-0.15 0.625,-0.1
  rectangle: 0.425,-0.675 0.625,-0.625
  region: 0.625,-0.375 0.425,-0.375 0.425,-0.425 0.625,-0.425
  region: 0.375,-0.425 0.375,-0.625 0.425,-0.625 0.425,-0.425
  region: 0.425,-0.425 0.425,-0.625 0.625,-0.625 0.625,-0.425
  region: 0.675,-0.625 0.675,-0.425 0.625,-0.425 0.625,-0.625
  rectangle: -0.625,-0.675 -0.425,-0.625
  region: -0.425,-0.375 -0.625,-0.375 -0.625,-0.425 -0.425,-0.425
  region: -0.675,-0.425 -0.675,-0.625 -0.625,-0.625 -0.625,-0.425
  region: -0.625,-0.425 -0.625,-0.625 -0.425,-0.625 -0.425,-0.425
  region: -0.375,-0.625 -0.375,-0.425 -0.425,-0.425 -0.425,-0.625
  rectangle: -0.1,-0.675 0.1,-0.625
  region: 0.1,-0.375 -0.1,-0.375 -0.1,-0.425 0.1,-0.425
  region: -0.15,-0.425 -0.15,-0.625 -0.1,-0.625 -0.1,-0.425
  region: -0.1,-0.425 -0.1,-0.625 0.1,-0.625 0.1,-0.425
  region: 0.15,-0.625 0.15,-0.425 0.1,-0.425 0.1,-0.625
  region: 0.15,0.425 0.15,0.625 0.1,0.625 0.1,0.425
  region: -0.1,0.625 -0.1,0.425 0.1,0.425 0.1,0.625
  region: -0.15,0.625 -0.15,0.425 -0.1,0.425 -0.1,0.625
  region: 0.1,0.675 -0.1,0.675 -0.1,0.625 0.1,0.625
  rectangle: -0.1,0.375 0.1,0.425
  region: -0.375,0.425 -0.375,0.625 -0.425,0.625 -0.425,0.425
  region: -0.625,0.625 -0.625,0.425 -0.425,0.425 -0.425,0.625
  region: -0.675,0.625 -0.675,0.425 -0.625,0.425 -0.625,0.625
  region: -0.425,0.675 -0.625,0.675 -0.625,0.625 -0.425,0.625
  rectangle: -0.625,0.375 -0.425,0.425
  region: 0.675,0.425 0.675,0.625 0.625,0.625 0.625,0.425
  region: 0.425,0.625 0.425,0.425 0.625,0.425 0.625,0.625
  region: 0.375,0.625 0.375,0.425 0.425,0.425 0.425,0.625
  region: 0.625,0.675 0.425,0.675 0.425,0.625 0.625,0.625
  rectangle: 0.425,0.375 0.625,0.425
Mechanical 13:
  lines w0.1: -0.705,-0.705 -0.705,0.705 0.705,0.705 0.705,-0.705 -0.705,-0.705
Mechanical 15:
  lines w0.1: -0.5,0 0.5,0 ; 0,-0.5 0,0.5 ; -0.805,-0.805 -0.805,0.805 0.805,0.805 0.805,-0.805 -0.805,-0.805
3D body: height 0.95, standoff 0, extent -0.704,-0.704 0.704,0.704

## SMD50P3X3-1.41X1.41-9V [mm] "Micro SMD, 9-Leads, Body 1.41x1.41mm, Pitch 0.5mm, NSC Recommended"
height 0.95
pads (9):
  round 0.165 smd paste-0.082 mask+0.05: A1(-0.5,0.5) A2(0,0.5) A3(0.5,0.5) B1(-0.5,0) B2(0,0) B3(0.5,0) C1(-0.5,-0.5) C2(0,-0.5) C3(0.5,-0.5)
Top Overlay:
  circle w0.1: c-0.81,0.81 r0.05
Top Paste:
  circle w0.05: c-0.425,-0.1 r0.025
  circle w0.05: c-0.625,0.1 r0.025
  circle w0.05: c-0.625,-0.1 r0.025
  circle w0.05: c-0.425,0.1 r0.025
  circle w0.05: c0.625,0.1 r0.025
  circle w0.05: c0.425,-0.1 r0.025
  circle w0.05: c0.425,0.1 r0.025
  circle w0.05: c0.625,-0.1 r0.025
  circle w0.05: c0.625,-0.625 r0.025
  circle w0.05: c0.425,-0.425 r0.025
  circle w0.05: c0.425,-0.625 r0.025
  circle w0.05: c0.625,-0.425 r0.025
  circle w0.05: c-0.425,-0.625 r0.025
  circle w0.05: c-0.625,-0.425 r0.025
  circle w0.05: c-0.625,-0.625 r0.025
  circle w0.05: c-0.425,-0.425 r0.025
  circle w0.05: c0.1,-0.625 r0.025
  circle w0.05: c-0.1,-0.425 r0.025
  circle w0.05: c-0.1,-0.625 r0.025
  circle w0.05: c0.1,-0.425 r0.025
  circle w0.05: c0.1,0.625 r0.025
  circle w0.05: c-0.1,0.425 r0.025
  circle w0.05: c-0.1,0.625 r0.025
  circle w0.05: c0.1,0.425 r0.025
  circle w0.05: c-0.425,0.625 r0.025
  circle w0.05: c-0.625,0.425 r0.025
  circle w0.05: c-0.625,0.625 r0.025
  circle w0.05: c-0.425,0.425 r0.025
  circle w0.05: c0.625,0.625 r0.025
  circle w0.05: c0.425,0.425 r0.025
  circle w0.05: c0.425,0.625 r0.025
  circle w0.05: c0.625,0.425 r0.025
  circle w0.05: c0.1,0.1 r0.025
  circle w0.05: c-0.1,-0.1 r0.025
  circle w0.05: c-0.1,0.1 r0.025
  circle w0.05: c0.1,-0.1 r0.025
  rectangle: -0.625,-0.15 -0.425,-0.1
  region: -0.425,0.15 -0.625,0.15 -0.625,0.1 -0.425,0.1
  region: -0.675,0.1 -0.675,-0.1 -0.625,-0.1 -0.625,0.1
  region: -0.625,0.1 -0.625,-0.1 -0.425,-0.1 -0.425,0.1
  region: -0.375,-0.1 -0.375,0.1 -0.425,0.1 -0.425,-0.1
  region: 0.675,-0.1 0.675,0.1 0.625,0.1 0.625,-0.1
  region: 0.425,0.1 0.425,-0.1 0.625,-0.1 0.625,0.1
  region: 0.375,0.1 0.375,-0.1 0.425,-0.1 0.425,0.1
  region: 0.625,0.15 0.425,0.15 0.425,0.1 0.625,0.1
  rectangle: 0.425,-0.15 0.625,-0.1
  rectangle: 0.425,-0.675 0.625,-0.625
  region: 0.625,-0.375 0.425,-0.375 0.425,-0.425 0.625,-0.425
  region: 0.375,-0.425 0.375,-0.625 0.425,-0.625 0.425,-0.425
  region: 0.425,-0.425 0.425,-0.625 0.625,-0.625 0.625,-0.425
  region: 0.675,-0.625 0.675,-0.425 0.625,-0.425 0.625,-0.625
  rectangle: -0.625,-0.675 -0.425,-0.625
  region: -0.425,-0.375 -0.625,-0.375 -0.625,-0.425 -0.425,-0.425
  region: -0.675,-0.425 -0.675,-0.625 -0.625,-0.625 -0.625,-0.425
  region: -0.625,-0.425 -0.625,-0.625 -0.425,-0.625 -0.425,-0.425
  region: -0.375,-0.625 -0.375,-0.425 -0.425,-0.425 -0.425,-0.625
  rectangle: -0.1,-0.675 0.1,-0.625
  region: 0.1,-0.375 -0.1,-0.375 -0.1,-0.425 0.1,-0.425
  region: -0.15,-0.425 -0.15,-0.625 -0.1,-0.625 -0.1,-0.425
  region: -0.1,-0.425 -0.1,-0.625 0.1,-0.625 0.1,-0.425
  region: 0.15,-0.625 0.15,-0.425 0.1,-0.425 0.1,-0.625
  region: 0.15,0.425 0.15,0.625 0.1,0.625 0.1,0.425
  region: -0.1,0.625 -0.1,0.425 0.1,0.425 0.1,0.625
  region: -0.15,0.625 -0.15,0.425 -0.1,0.425 -0.1,0.625
  region: 0.1,0.675 -0.1,0.675 -0.1,0.625 0.1,0.625
  rectangle: -0.1,0.375 0.1,0.425
  region: -0.375,0.425 -0.375,0.625 -0.425,0.625 -0.425,0.425
  region: -0.625,0.625 -0.625,0.425 -0.425,0.425 -0.425,0.625
  region: -0.675,0.625 -0.675,0.425 -0.625,0.425 -0.625,0.625
  region: -0.425,0.675 -0.625,0.675 -0.625,0.625 -0.425,0.625
  rectangle: -0.625,0.375 -0.425,0.425
  region: 0.675,0.425 0.675,0.625 0.625,0.625 0.625,0.425
  region: 0.425,0.625 0.425,0.425 0.625,0.425 0.625,0.625
  region: 0.375,0.625 0.375,0.425 0.425,0.425 0.425,0.625
  region: 0.625,0.675 0.425,0.675 0.425,0.625 0.625,0.625
  rectangle: 0.425,0.375 0.625,0.425
  region: 0.15,-0.1 0.15,0.1 0.1,0.1 0.1,-0.1
  region: -0.1,0.1 -0.1,-0.1 0.1,-0.1 0.1,0.1
  region: -0.15,0.1 -0.15,-0.1 -0.1,-0.1 -0.1,0.1
  region: 0.1,0.15 -0.1,0.15 -0.1,0.1 0.1,0.1
  rectangle: -0.1,-0.15 0.1,-0.1
Mechanical 13:
  lines w0.1: -0.705,-0.705 0.705,-0.705 0.705,0.705 -0.705,0.705 -0.705,-0.705
Mechanical 15:
  lines w0.1: -0.5,0 0.5,0 ; 0,-0.5 0,0.5 ; -0.805,-0.805 0.805,-0.805 0.805,0.805 -0.805,0.805 -0.805,-0.805
3D body: height 0.95, standoff 0, extent -0.704,-0.704 0.704,0.704

## SMD50P3X3-1.41X1.41X0.58-8V [mm] "Micro SMD, 8-Leads, Body 1.41x1.41mm, Pitch 0.5mm, NSC Recommended"
height 0.58
pads (8):
  round 0.165 smd paste-0.082 mask+0.05: A1(-0.5,0.5) A2(0,0.5) A3(0.5,0.5) B1(-0.5,0) B3(0.5,0) C1(-0.5,-0.5) C2(0,-0.5) C3(0.5,-0.5)
Top Overlay:
  circle w0.1: c-0.81,0.81 r0.05
Top Paste:
  circle w0.05: c0.425,-0.625 r0.025
  circle w0.05: c0.625,-0.425 r0.025
  circle w0.05: c0.425,-0.425 r0.025
  circle w0.05: c0.625,-0.625 r0.025
  circle w0.05: c-0.1,-0.625 r0.025
  circle w0.05: c0.1,-0.425 r0.025
  circle w0.05: c-0.1,-0.425 r0.025
  circle w0.05: c0.1,-0.625 r0.025
  circle w0.05: c-0.625,-0.625 r0.025
  circle w0.05: c-0.425,-0.425 r0.025
  circle w0.05: c-0.625,-0.425 r0.025
  circle w0.05: c-0.425,-0.625 r0.025
  circle w0.05: c0.425,-0.1 r0.025
  circle w0.05: c0.625,0.1 r0.025
  circle w0.05: c0.425,0.1 r0.025
  circle w0.05: c0.625,-0.1 r0.025
  circle w0.05: c-0.625,-0.1 r0.025
  circle w0.05: c-0.425,0.1 r0.025
  circle w0.05: c-0.625,0.1 r0.025
  circle w0.05: c-0.425,-0.1 r0.025
  circle w0.05: c0.425,0.425 r0.025
  circle w0.05: c0.625,0.625 r0.025
  circle w0.05: c0.425,0.625 r0.025
  circle w0.05: c0.625,0.425 r0.025
  circle w0.05: c-0.1,0.425 r0.025
  circle w0.05: c0.1,0.625 r0.025
  circle w0.05: c-0.1,0.625 r0.025
  circle w0.05: c0.1,0.425 r0.025
  circle w0.05: c-0.625,0.425 r0.025
  circle w0.05: c-0.425,0.625 r0.025
  circle w0.05: c-0.625,0.625 r0.025
  circle w0.05: c-0.425,0.425 r0.025
  region: 0.625,-0.625 0.425,-0.625 0.425,-0.675 0.625,-0.675
  rectangle: 0.425,-0.625 0.625,-0.425
  rectangle: 0.425,-0.425 0.625,-0.375
  region: 0.425,-0.625 0.425,-0.425 0.375,-0.425 0.375,-0.625
  region: 0.625,-0.425 0.625,-0.625 0.675,-0.625 0.675,-0.425
  region: 0.1,-0.625 -0.1,-0.625 -0.1,-0.675 0.1,-0.675
  rectangle: -0.1,-0.625 0.1,-0.425
  rectangle: -0.1,-0.425 0.1,-0.375
  region: -0.1,-0.625 -0.1,-0.425 -0.15,-0.425 -0.15,-0.625
  region: 0.1,-0.425 0.1,-0.625 0.15,-0.625 0.15,-0.425
  region: -0.425,-0.625 -0.625,-0.625 -0.625,-0.675 -0.425,-0.675
  rectangle: -0.625,-0.625 -0.425,-0.425
  rectangle: -0.625,-0.425 -0.425,-0.375
  region: -0.625,-0.625 -0.625,-0.425 -0.675,-0.425 -0.675,-0.625
  region: -0.425,-0.425 -0.425,-0.625 -0.375,-0.625 -0.375,-0.425
  region: 0.625,-0.1 0.425,-0.1 0.425,-0.15 0.625,-0.15
  rectangle: 0.425,-0.1 0.625,0.1
  rectangle: 0.425,0.1 0.625,0.15
  region: 0.425,-0.1 0.425,0.1 0.375,0.1 0.375,-0.1
  region: 0.625,0.1 0.625,-0.1 0.675,-0.1 0.675,0.1
  region: -0.425,-0.1 -0.625,-0.1 -0.625,-0.15 -0.425,-0.15
  rectangle: -0.625,-0.1 -0.425,0.1
  rectangle: -0.625,0.1 -0.425,0.15
  region: -0.625,-0.1 -0.625,0.1 -0.675,0.1 -0.675,-0.1
  region: -0.425,0.1 -0.425,-0.1 -0.375,-0.1 -0.375,0.1
  region: 0.625,0.425 0.425,0.425 0.425,0.375 0.625,0.375
  rectangle: 0.425,0.425 0.625,0.625
  rectangle: 0.425,0.625 0.625,0.675
  region: 0.425,0.425 0.425,0.625 0.375,0.625 0.375,0.425
  region: 0.625,0.625 0.625,0.425 0.675,0.425 0.675,0.625
  region: 0.1,0.425 -0.1,0.425 -0.1,0.375 0.1,0.375
  rectangle: -0.1,0.425 0.1,0.625
  rectangle: -0.1,0.625 0.1,0.675
  region: -0.1,0.425 -0.1,0.625 -0.15,0.625 -0.15,0.425
  region: 0.1,0.625 0.1,0.425 0.15,0.425 0.15,0.625
  region: -0.425,0.425 -0.625,0.425 -0.625,0.375 -0.425,0.375
  rectangle: -0.625,0.425 -0.425,0.625
  rectangle: -0.625,0.625 -0.425,0.675
  region: -0.625,0.425 -0.625,0.625 -0.675,0.625 -0.675,0.425
  region: -0.425,0.625 -0.425,0.425 -0.375,0.425 -0.375,0.625
Mechanical 13:
  lines w0.1: -0.705,-0.705 0.705,-0.705 0.705,0.705 -0.705,0.705 -0.705,-0.705
Mechanical 15:
  lines w0.1: -0.5,0 0.5,0 ; 0,-0.5 0,0.5 ; -0.805,-0.805 0.805,-0.805 0.805,0.805 -0.805,0.805 -0.805,-0.805
3D body: height 0.58, standoff 0, extent -0.705,-0.705 0.705,0.705

## SMD50P3X3-1.41X1.41X0.58-9V [mm] "Micro SMD, 9-Leads, Body 1.41x1.41mm, Pitch 0.5mm, NSC Recommended"
height 0.58
pads (9):
  round 0.165 smd paste-0.082 mask+0.05: A1(-0.5,0.5) A2(0,0.5) A3(0.5,0.5) B1(-0.5,0) B2(0,0) B3(0.5,0) C1(-0.5,-0.5) C2(0,-0.5) C3(0.5,-0.5)
Top Overlay:
  circle w0.1: c-0.81,0.81 r0.05
Top Paste:
  circle w0.05: c-0.425,0.425 r0.025
  circle w0.05: c-0.625,0.625 r0.025
  circle w0.05: c-0.425,0.625 r0.025
  circle w0.05: c-0.625,0.425 r0.025
  circle w0.05: c0.1,0.425 r0.025
  circle w0.05: c-0.1,0.625 r0.025
  circle w0.05: c0.1,0.625 r0.025
  circle w0.05: c-0.1,0.425 r0.025
  circle w0.05: c0.625,0.425 r0.025
  circle w0.05: c0.425,0.625 r0.025
  circle w0.05: c0.625,0.625 r0.025
  circle w0.05: c0.425,0.425 r0.025
  circle w0.05: c-0.425,-0.1 r0.025
  circle w0.05: c-0.625,0.1 r0.025
  circle w0.05: c-0.425,0.1 r0.025
  circle w0.05: c-0.625,-0.1 r0.025
  circle w0.05: c0.1,-0.1 r0.025
  circle w0.05: c-0.1,0.1 r0.025
  circle w0.05: c0.1,0.1 r0.025
  circle w0.05: c-0.1,-0.1 r0.025
  circle w0.05: c0.625,-0.1 r0.025
  circle w0.05: c0.425,0.1 r0.025
  circle w0.05: c0.625,0.1 r0.025
  circle w0.05: c0.425,-0.1 r0.025
  circle w0.05: c-0.425,-0.625 r0.025
  circle w0.05: c-0.625,-0.425 r0.025
  circle w0.05: c-0.425,-0.425 r0.025
  circle w0.05: c-0.625,-0.625 r0.025
  circle w0.05: c0.1,-0.625 r0.025
  circle w0.05: c-0.1,-0.425 r0.025
  circle w0.05: c0.1,-0.425 r0.025
  circle w0.05: c-0.1,-0.625 r0.025
  circle w0.05: c0.625,-0.625 r0.025
  circle w0.05: c0.425,-0.425 r0.025
  circle w0.05: c0.625,-0.425 r0.025
  circle w0.05: c0.425,-0.625 r0.025
  region: -0.425,0.625 -0.425,0.425 -0.375,0.425 -0.375,0.625
  region: -0.625,0.425 -0.625,0.625 -0.675,0.625 -0.675,0.425
  rectangle: -0.625,0.625 -0.425,0.675
  rectangle: -0.625,0.425 -0.425,0.625
  region: -0.425,0.425 -0.625,0.425 -0.625,0.375 -0.425,0.375
  region: 0.1,0.625 0.1,0.425 0.15,0.425 0.15,0.625
  region: -0.1,0.425 -0.1,0.625 -0.15,0.625 -0.15,0.425
  rectangle: -0.1,0.625 0.1,0.675
  rectangle: -0.1,0.425 0.1,0.625
  region: 0.1,0.425 -0.1,0.425 -0.1,0.375 0.1,0.375
  region: 0.625,0.625 0.625,0.425 0.675,0.425 0.675,0.625
  region: 0.425,0.425 0.425,0.625 0.375,0.625 0.375,0.425
  rectangle: 0.425,0.625 0.625,0.675
  rectangle: 0.425,0.425 0.625,0.625
  region: 0.625,0.425 0.425,0.425 0.425,0.375 0.625,0.375
  region: -0.425,0.1 -0.425,-0.1 -0.375,-0.1 -0.375,0.1
  region: -0.625,-0.1 -0.625,0.1 -0.675,0.1 -0.675,-0.1
  rectangle: -0.625,0.1 -0.425,0.15
  rectangle: -0.625,-0.1 -0.425,0.1
  region: -0.425,-0.1 -0.625,-0.1 -0.625,-0.15 -0.425,-0.15
  region: 0.1,0.1 0.1,-0.1 0.15,-0.1 0.15,0.1
  region: -0.1,-0.1 -0.1,0.1 -0.15,0.1 -0.15,-0.1
  rectangle: -0.1,0.1 0.1,0.15
  rectangle: -0.1,-0.1 0.1,0.1
  region: 0.1,-0.1 -0.1,-0.1 -0.1,-0.15 0.1,-0.15
  region: 0.625,0.1 0.625,-0.1 0.675,-0.1 0.675,0.1
  region: 0.425,-0.1 0.425,0.1 0.375,0.1 0.375,-0.1
  rectangle: 0.425,0.1 0.625,0.15
  rectangle: 0.425,-0.1 0.625,0.1
  region: 0.625,-0.1 0.425,-0.1 0.425,-0.15 0.625,-0.15
  region: -0.425,-0.425 -0.425,-0.625 -0.375,-0.625 -0.375,-0.425
  region: -0.625,-0.625 -0.625,-0.425 -0.675,-0.425 -0.675,-0.625
  rectangle: -0.625,-0.425 -0.425,-0.375
  rectangle: -0.625,-0.625 -0.425,-0.425
  region: -0.425,-0.625 -0.625,-0.625 -0.625,-0.675 -0.425,-0.675
  region: 0.1,-0.425 0.1,-0.625 0.15,-0.625 0.15,-0.425
  region: -0.1,-0.625 -0.1,-0.425 -0.15,-0.425 -0.15,-0.625
  rectangle: -0.1,-0.425 0.1,-0.375
  rectangle: -0.1,-0.625 0.1,-0.425
  region: 0.1,-0.625 -0.1,-0.625 -0.1,-0.675 0.1,-0.675
  region: 0.625,-0.425 0.625,-0.625 0.675,-0.625 0.675,-0.425
  region: 0.425,-0.625 0.425,-0.425 0.375,-0.425 0.375,-0.625
  rectangle: 0.425,-0.425 0.625,-0.375
  rectangle: 0.425,-0.625 0.625,-0.425
  region: 0.625,-0.625 0.425,-0.625 0.425,-0.675 0.625,-0.675
Mechanical 13:
  lines w0.1: -0.705,-0.705 -0.705,0.705 0.705,0.705 0.705,-0.705 -0.705,-0.705
Mechanical 15:
  lines w0.1: -0.5,0 0.5,0 ; 0,-0.5 0,0.5 ; -0.805,-0.805 -0.805,0.805 0.805,0.805 0.805,-0.805 -0.805,-0.805
3D body: height 0.58, standoff 0, extent -0.705,-0.705 0.705,0.705

## SMD50P3X3-1.41X1.95-8V [mm] "Micro SMD, 8-Leads, Body 1.95x1.41mm, Pitch 0.5mm, NSC Recommended"
height 0.58
pads (8):
  round 0.165 smd paste-0.082 mask+0.05: A1(-0.5,0.5) A2(0,0.5) A3(0.5,0.5) B1(-0.5,0) B3(0.5,0) C1(-0.5,-0.5) C2(0,-0.5) C3(0.5,-0.5)
Top Overlay:
  circle w0.1: c-0.82,1.07 r0.05
Top Paste:
  circle w0.05: c0.625,0.425 r0.025
  circle w0.05: c0.425,0.625 r0.025
  circle w0.05: c0.425,0.425 r0.025
  circle w0.05: c0.625,0.625 r0.025
  circle w0.05: c-0.425,0.425 r0.025
  circle w0.05: c-0.625,0.625 r0.025
  circle w0.05: c-0.625,0.425 r0.025
  circle w0.05: c-0.425,0.625 r0.025
  circle w0.05: c0.1,0.425 r0.025
  circle w0.05: c-0.1,0.625 r0.025
  circle w0.05: c-0.1,0.425 r0.025
  circle w0.05: c0.1,0.625 r0.025
  circle w0.05: c0.1,-0.425 r0.025
  circle w0.05: c-0.1,-0.625 r0.025
  circle w0.05: c-0.1,-0.425 r0.025
  circle w0.05: c0.1,-0.625 r0.025
  circle w0.05: c-0.425,-0.425 r0.025
  circle w0.05: c-0.625,-0.625 r0.025
  circle w0.05: c-0.625,-0.425 r0.025
  circle w0.05: c-0.425,-0.625 r0.025
  circle w0.05: c0.625,-0.425 r0.025
  circle w0.05: c0.425,-0.625 r0.025
  circle w0.05: c0.425,-0.425 r0.025
  circle w0.05: c0.625,-0.625 r0.025
  circle w0.05: c0.625,-0.1 r0.025
  circle w0.05: c0.425,0.1 r0.025
  circle w0.05: c0.425,-0.1 r0.025
  circle w0.05: c0.625,0.1 r0.025
  circle w0.05: c-0.425,0.1 r0.025
  circle w0.05: c-0.625,-0.1 r0.025
  circle w0.05: c-0.625,0.1 r0.025
  circle w0.05: c-0.425,-0.1 r0.025
  rectangle: 0.425,0.375 0.625,0.425
  region: 0.625,0.675 0.425,0.675 0.425,0.625 0.625,0.625
  region: 0.375,0.625 0.375,0.425 0.425,0.425 0.425,0.625
  region: 0.425,0.625 0.425,0.425 0.625,0.425 0.625,0.625
  region: 0.675,0.425 0.675,0.625 0.625,0.625 0.625,0.425
  rectangle: -0.625,0.375 -0.425,0.425
  region: -0.425,0.675 -0.625,0.675 -0.625,0.625 -0.425,0.625
  region: -0.675,0.625 -0.675,0.425 -0.625,0.425 -0.625,0.625
  region: -0.625,0.625 -0.625,0.425 -0.425,0.425 -0.425,0.625
  region: -0.375,0.425 -0.375,0.625 -0.425,0.625 -0.425,0.425
  rectangle: -0.1,0.375 0.1,0.425
  region: 0.1,0.675 -0.1,0.675 -0.1,0.625 0.1,0.625
  region: -0.15,0.625 -0.15,0.425 -0.1,0.425 -0.1,0.625
  region: -0.1,0.625 -0.1,0.425 0.1,0.425 0.1,0.625
  region: 0.15,0.425 0.15,0.625 0.1,0.625 0.1,0.425
  region: 0.15,-0.625 0.15,-0.425 0.1,-0.425 0.1,-0.625
  region: -0.1,-0.425 -0.1,-0.625 0.1,-0.625 0.1,-0.425
  region: -0.15,-0.425 -0.15,-0.625 -0.1,-0.625 -0.1,-0.425
  region: 0.1,-0.375 -0.1,-0.375 -0.1,-0.425 0.1,-0.425
  rectangle: -0.1,-0.675 0.1,-0.625
  region: -0.375,-0.625 -0.375,-0.425 -0.425,-0.425 -0.425,-0.625
  region: -0.625,-0.425 -0.625,-0.625 -0.425,-0.625 -0.425,-0.425
  region: -0.675,-0.425 -0.675,-0.625 -0.625,-0.625 -0.625,-0.425
  region: -0.425,-0.375 -0.625,-0.375 -0.625,-0.425 -0.425,-0.425
  rectangle: -0.625,-0.675 -0.425,-0.625
  region: 0.675,-0.625 0.675,-0.425 0.625,-0.425 0.625,-0.625
  region: 0.425,-0.425 0.425,-0.625 0.625,-0.625 0.625,-0.425
  region: 0.375,-0.425 0.375,-0.625 0.425,-0.625 0.425,-0.425
  region: 0.625,-0.375 0.425,-0.375 0.425,-0.425 0.625,-0.425
  rectangle: 0.425,-0.675 0.625,-0.625
  rectangle: 0.425,-0.15 0.625,-0.1
  region: 0.625,0.15 0.425,0.15 0.425,0.1 0.625,0.1
  region: 0.375,0.1 0.375,-0.1 0.425,-0.1 0.425,0.1
  region: 0.425,0.1 0.425,-0.1 0.625,-0.1 0.625,0.1
  region: 0.675,-0.1 0.675,0.1 0.625,0.1 0.625,-0.1
  region: -0.375,-0.1 -0.375,0.1 -0.425,0.1 -0.425,-0.1
  region: -0.625,0.1 -0.625,-0.1 -0.425,-0.1 -0.425,0.1
  region: -0.675,0.1 -0.675,-0.1 -0.625,-0.1 -0.625,0.1
  region: -0.425,0.15 -0.625,0.15 -0.625,0.1 -0.425,0.1
  rectangle: -0.625,-0.15 -0.425,-0.1
Mechanical 13:
  lines w0.1: -0.705,-0.975 0.705,-0.975 0.705,0.975 -0.705,0.975 -0.705,-0.975
Mechanical 15:
  lines w0.1: -0.5,0 0.5,0 ; 0,-0.5 0,0.5 ; -0.805,-1.075 0.805,-1.075 0.805,1.075 -0.805,1.075 -0.805,-1.075
3D body: height 0.58, standoff 0, extent -0.704,-0.974 0.704,0.974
